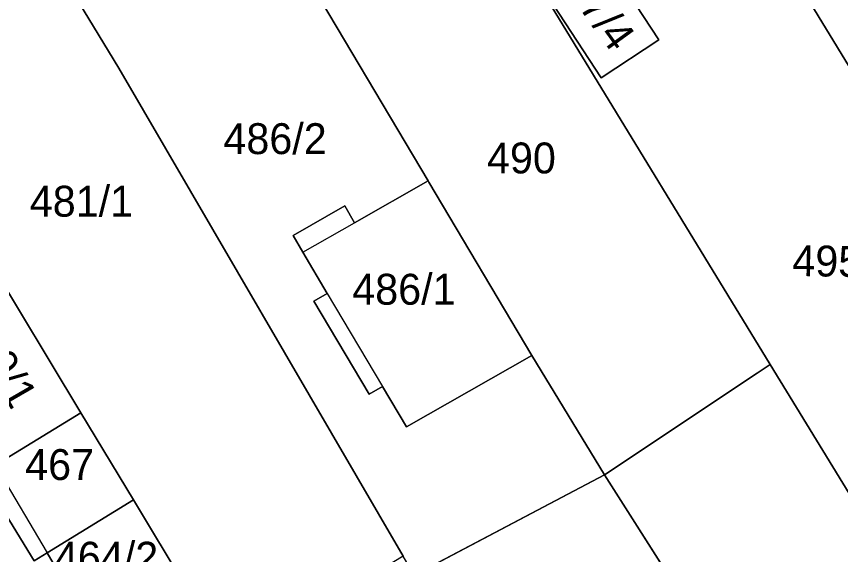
# Model space of a CAD drawing. Extents: x -263943 to -261149, y -1236934 to -1230686.
# Drawn here: x -262746.5 to -262693.2, y -1235535.8 to -1235500.9 of the extents above; entities that cross this region are included whole.
import ezdxf

# ---------------------------------------------------------------- set-up
doc = ezdxf.new("R2010")
doc.units = 0
for name, color, linetype in [('body_kn', 7, 'Continuous'), ('kladpar_druhypozemkov', 7, 'Continuous'), ('kladpar_hranice', 7, 'Continuous'), ('kladpar_parcelnecisla', 7, 'Continuous'), ('kladpar_plochy', 7, 'Continuous'), ('zappar_hrandruhpozemk', 7, 'Continuous')]:
    doc.layers.add(name, color=color, linetype=linetype)

msp = doc.modelspace()

# ---------------------------------------------------------------- linework, layer by layer
at = {"layer": 'body_kn'}
for p, q in [((-262704.92, -1235502.47), (-262704.92, -1235502.47)), ((-262739.92, -1235504.3), (-262739.92, -1235504.3)), ((-262708.67, -1235504.92), (-262708.67, -1235504.92)), ((-262719.87, -1235511.58), (-262719.87, -1235511.58)), ((-262719.82, -1235511.67), (-262719.82, -1235511.67)), ((-262725.27, -1235513.22), (-262725.27, -1235513.22)), ((-262724.65, -1235514.3), (-262724.65, -1235514.3)), ((-262728.61, -1235515.12), (-262728.61, -1235515.12)), ((-262728, -1235516.21), (-262728, -1235516.21)), ((-262728, -1235516.21), (-262728, -1235516.21)), ((-262726.41, -1235518.88), (-262726.41, -1235518.88)), ((-262726.41, -1235518.88), (-262726.41, -1235518.88)), ((-262727.27, -1235519.39), (-262727.27, -1235519.39)), ((-262713.16, -1235522.89), (-262713.16, -1235522.89)), ((-262697.71, -1235523.48), (-262697.71, -1235523.48)), ((-262698.56, -1235524.05), (-262698.56, -1235524.05)), ((-262722.84, -1235524.9), (-262722.84, -1235524.9)), ((-262722.84, -1235524.9), (-262722.84, -1235524.9)), ((-262723.7, -1235525.41), (-262723.7, -1235525.41)), ((-262723.7, -1235525.41), (-262723.7, -1235525.41)), ((-262742.37, -1235526.62), (-262742.37, -1235526.62)), ((-262721.28, -1235527.52), (-262721.28, -1235527.52)), ((-262708.44, -1235530.63), (-262708.44, -1235530.63)), ((-262708.44, -1235530.63), (-262708.44, -1235530.63)), ((-262738.97, -1235532.25), (-262738.97, -1235532.25)), ((-262744.56, -1235535.68), (-262744.56, -1235535.68)), ((-262744.56, -1235535.68), (-262744.56, -1235535.68))]:
    msp.add_line(p, q, dxfattribs=at)
at = {"layer": 'kladpar_druhypozemkov'}
for p, q in [((-262729.29, -1235507.92), (-262729.29, -1235507.92)), ((-262713.88, -1235509.06), (-262713.88, -1235509.06)), ((-262743.18, -1235511.56), (-262743.18, -1235511.56)), ((-262720.91, -1235517.64), (-262720.91, -1235517.64)), ((-262744.08, -1235529.36), (-262744.08, -1235529.36)), ((-262740.43, -1235535.31), (-262740.43, -1235535.31))]:
    msp.add_line(p, q, dxfattribs=at)
at = {"layer": 'kladpar_hranice'}
for points in [[(-262732.68, -1235542.66), (-262735.56, -1235537.92), (-262738.97, -1235532.25), (-262742.37, -1235526.62), (-262748.42, -1235516.59), (-262751.86, -1235510.9), (-262754.4, -1235506.7), (-262759.41, -1235498.41), (-262755.64, -1235496.17), (-262761.46, -1235480.43), (-262761.23, -1235480.29), (-262759.33, -1235483.39), (-262754.85, -1235480.58), (-262756.66, -1235477.56), (-262756.22, -1235477.3), (-262753.4, -1235482.02), (-262743.5, -1235498.38), (-262739.92, -1235504.3), (-262721.5, -1235535.89), (-262732.68, -1235542.66)], [(-262679.94, -1235550.86), (-262683.58, -1235545.66), (-262690.16, -1235535.81), (-262691.29, -1235533.96), (-262697.71, -1235523.48), (-262711.91, -1235500.27), (-262711.77, -1235500.18), (-262708.67, -1235504.92), (-262704.92, -1235502.47), (-262707.96, -1235497.85), (-262708.3, -1235498.02), (-262708.9, -1235497), (-262707.37, -1235494.42), (-262706.2, -1235493.57), (-262701.27, -1235490), (-262696.88, -1235497.18), (-262679.03, -1235526.4), (-262678.1, -1235528.02), (-262677.34, -1235529.21), (-262668.48, -1235542.55), (-262672.73, -1235545.63)], [(-262708.44, -1235530.63), (-262713.16, -1235522.89), (-262719.82, -1235511.67), (-262719.87, -1235511.58), (-262728.27, -1235497.45), (-262717.74, -1235491.26), (-262713.04, -1235498.53), (-262712.01, -1235500.12), (-262711.91, -1235500.27), (-262697.71, -1235523.48), (-262698.56, -1235524.05), (-262708.44, -1235530.63)], [(-262723.7, -1235525.41), (-262722.84, -1235524.9), (-262721.28, -1235527.52), (-262713.16, -1235522.89), (-262708.44, -1235530.63), (-262720.78, -1235537.12), (-262721.5, -1235535.89), (-262739.92, -1235504.3), (-262743.5, -1235498.38), (-262737.23, -1235494.67), (-262732.24, -1235491.71), (-262731.82, -1235491.46), (-262728.27, -1235497.45), (-262719.87, -1235511.58), (-262724.65, -1235514.3), (-262725.27, -1235513.22), (-262728.61, -1235515.12), (-262728, -1235516.21), (-262726.41, -1235518.88), (-262727.27, -1235519.39), (-262723.7, -1235525.41)], [(-262677.34, -1235529.21), (-262678.1, -1235528.02), (-262679.03, -1235526.4), (-262696.88, -1235497.18), (-262691.95, -1235494), (-262690.77, -1235493.24), (-262678.97, -1235512.32), (-262671.29, -1235524.22), (-262671.04, -1235524.56), (-262677.34, -1235529.21)], [(-262707.37, -1235494.42), (-262708.9, -1235497), (-262708.3, -1235498.02), (-262707.96, -1235497.85), (-262704.92, -1235502.47), (-262708.67, -1235504.92), (-262711.77, -1235500.18), (-262711.91, -1235500.27), (-262712.01, -1235500.12), (-262713.04, -1235498.53), (-262707.37, -1235494.42)], [(-262722.84, -1235524.9), (-262723.7, -1235525.41), (-262727.27, -1235519.39), (-262726.41, -1235518.88), (-262728, -1235516.21), (-262728.61, -1235515.12), (-262725.27, -1235513.22), (-262724.65, -1235514.3), (-262719.87, -1235511.58), (-262719.82, -1235511.67), (-262713.16, -1235522.89), (-262721.28, -1235527.52), (-262722.84, -1235524.9)], [(-262754.1, -1235519.97), (-262753.45, -1235519.58), (-262748.42, -1235516.59), (-262742.37, -1235526.62), (-262747.27, -1235529.61), (-262747.92, -1235530.01), (-262754.1, -1235519.97)], [(-262661.06, -1235580.01), (-262667.68, -1235584.04), (-262669.56, -1235581), (-262673.39, -1235583.28), (-262671.5, -1235586.37), (-262672.55, -1235587.01), (-262678.55, -1235577.58), (-262681.07, -1235573.62), (-262686.13, -1235565.68), (-262708.44, -1235530.63), (-262698.56, -1235524.05), (-262697.71, -1235523.48), (-262691.29, -1235533.96), (-262690.16, -1235535.81), (-262683.58, -1235545.66), (-262679.94, -1235550.86), (-262678.88, -1235552.37), (-262661.06, -1235580.01)], [(-262745.4, -1235536.19), (-262748.86, -1235530.58), (-262747.92, -1235530.01), (-262747.27, -1235529.61), (-262742.37, -1235526.62), (-262738.97, -1235532.25), (-262744.56, -1235535.68), (-262745.4, -1235536.19)], [(-262748.86, -1235530.58), (-262745.4, -1235536.19), (-262744.56, -1235535.68), (-262741.18, -1235541.47), (-262735.77, -1235548.28), (-262731.8, -1235554.23), (-262727.84, -1235560.95), (-262727.59, -1235562.73), (-262721.36, -1235572.81), (-262722.02, -1235573.19), (-262713.22, -1235586.8), (-262714.08, -1235587.33), (-262729.97, -1235563.83), (-262735.96, -1235553.03), (-262747.28, -1235537.2)], [(-262720.78, -1235537.12), (-262708.44, -1235530.63), (-262686.13, -1235565.68), (-262698.45, -1235573.07)], [(-262744.56, -1235535.68), (-262738.97, -1235532.25), (-262735.56, -1235537.92), (-262741.18, -1235541.47), (-262744.56, -1235535.68)]]:
    msp.add_lwpolyline(points, dxfattribs=at)
at = {"layer": 'kladpar_plochy'}
for p, q in [((-262720.78, -1235537.12), (-262708.44, -1235530.63)), ((-262708.44, -1235530.63), (-262686.13, -1235565.68))]:
    msp.add_line(p, q, dxfattribs=at)
for points in [[(-262732.68, -1235542.66), (-262735.56, -1235537.92), (-262738.97, -1235532.25), (-262742.37, -1235526.62), (-262748.42, -1235516.59), (-262751.86, -1235510.9), (-262754.4, -1235506.7), (-262759.41, -1235498.41), (-262755.64, -1235496.17), (-262761.46, -1235480.43), (-262761.23, -1235480.29), (-262759.33, -1235483.39), (-262754.85, -1235480.58), (-262756.66, -1235477.56), (-262756.22, -1235477.3), (-262753.4, -1235482.02), (-262743.5, -1235498.38), (-262739.92, -1235504.3), (-262721.5, -1235535.89)], [(-262679.94, -1235550.86), (-262683.58, -1235545.66), (-262690.16, -1235535.81), (-262691.29, -1235533.96), (-262697.71, -1235523.48), (-262711.91, -1235500.27), (-262711.77, -1235500.18), (-262708.67, -1235504.92), (-262704.92, -1235502.47), (-262707.96, -1235497.85), (-262708.3, -1235498.02), (-262708.9, -1235497), (-262707.37, -1235494.42), (-262706.2, -1235493.57), (-262701.27, -1235490), (-262696.88, -1235497.18), (-262679.03, -1235526.4), (-262678.1, -1235528.02), (-262677.34, -1235529.21), (-262668.48, -1235542.55), (-262672.73, -1235545.63), (-262685.17, -1235526.28), (-262686.8, -1235527.37), (-262674.32, -1235546.78)], [(-262708.44, -1235530.63), (-262713.16, -1235522.89), (-262719.82, -1235511.67), (-262719.87, -1235511.58), (-262728.27, -1235497.45), (-262717.74, -1235491.26), (-262713.04, -1235498.53), (-262712.01, -1235500.12), (-262711.91, -1235500.27), (-262697.71, -1235523.48), (-262698.56, -1235524.05)], [(-262723.7, -1235525.41), (-262722.84, -1235524.9), (-262721.28, -1235527.52), (-262713.16, -1235522.89), (-262708.44, -1235530.63), (-262720.78, -1235537.12), (-262721.5, -1235535.89), (-262739.92, -1235504.3), (-262743.5, -1235498.38), (-262737.23, -1235494.67), (-262732.24, -1235491.71), (-262731.82, -1235491.46), (-262728.27, -1235497.45), (-262719.87, -1235511.58), (-262724.65, -1235514.3), (-262725.27, -1235513.22), (-262728.61, -1235515.12), (-262728, -1235516.21), (-262726.41, -1235518.88), (-262727.27, -1235519.39)], [(-262677.34, -1235529.21), (-262678.1, -1235528.02), (-262679.03, -1235526.4), (-262696.88, -1235497.18), (-262691.95, -1235494), (-262690.77, -1235493.24), (-262678.97, -1235512.32), (-262671.29, -1235524.22), (-262671.04, -1235524.56)], [(-262707.37, -1235494.42), (-262708.9, -1235497), (-262708.3, -1235498.02), (-262707.96, -1235497.85), (-262704.92, -1235502.47), (-262708.67, -1235504.92), (-262711.77, -1235500.18), (-262711.91, -1235500.27), (-262712.01, -1235500.12), (-262713.04, -1235498.53)], [(-262722.84, -1235524.9), (-262723.7, -1235525.41), (-262727.27, -1235519.39), (-262726.41, -1235518.88), (-262728, -1235516.21), (-262728.61, -1235515.12), (-262725.27, -1235513.22), (-262724.65, -1235514.3), (-262719.87, -1235511.58), (-262719.82, -1235511.67), (-262713.16, -1235522.89), (-262721.28, -1235527.52)], [(-262754.1, -1235519.97), (-262753.45, -1235519.58), (-262748.42, -1235516.59), (-262742.37, -1235526.62), (-262747.27, -1235529.61), (-262747.92, -1235530.01)], [(-262661.06, -1235580.01), (-262667.68, -1235584.04), (-262669.56, -1235581), (-262673.39, -1235583.28), (-262671.5, -1235586.37), (-262672.55, -1235587.01), (-262678.55, -1235577.58), (-262681.07, -1235573.62), (-262686.13, -1235565.68), (-262708.44, -1235530.63), (-262698.56, -1235524.05), (-262697.71, -1235523.48), (-262691.29, -1235533.96), (-262690.16, -1235535.81), (-262683.58, -1235545.66), (-262679.94, -1235550.86), (-262678.88, -1235552.37)], [(-262745.4, -1235536.19), (-262748.86, -1235530.58), (-262747.92, -1235530.01), (-262747.27, -1235529.61), (-262742.37, -1235526.62), (-262738.97, -1235532.25), (-262744.56, -1235535.68)], [(-262744.56, -1235535.68), (-262738.97, -1235532.25), (-262735.56, -1235537.92), (-262741.18, -1235541.47)]]:
    msp.add_lwpolyline(points, close=True, dxfattribs=at)
msp.add_lwpolyline([(-262748.86, -1235530.58), (-262745.4, -1235536.19), (-262744.56, -1235535.68), (-262741.18, -1235541.47), (-262735.77, -1235548.28), (-262731.8, -1235554.23), (-262727.84, -1235560.95), (-262727.59, -1235562.73), (-262721.36, -1235572.81), (-262722.02, -1235573.19), (-262713.22, -1235586.8), (-262714.08, -1235587.33), (-262729.97, -1235563.83), (-262735.96, -1235553.03), (-262747.28, -1235537.2)], dxfattribs=at)
at = {"layer": 'zappar_hrandruhpozemk'}
for p, q in [((-262728, -1235516.21), (-262724.65, -1235514.3)), ((-262726.41, -1235518.88), (-262722.84, -1235524.9)), ((-262747.92, -1235530.01), (-262744.56, -1235535.68))]:
    msp.add_line(p, q, dxfattribs=at)

# ---------------------------------------------------------------- texts
at = {"layer": 'kladpar_parcelnecisla'}
for s, rotation, p in [('497/4', 306, (-262711.905, -1235497.928)), ('495/1', 359, (-262696.292, -1235517.746)), ('470/1', 300, (-262750.183, -1235520.7))]:
    msp.add_text(s, height=2, rotation=rotation, dxfattribs=at).set_placement(p)
for s, p in [('486/2', (-262733.137, -1235509.86)), ('490', (-262716.06, -1235511.11)), ('481/1', (-262745.682, -1235513.91)), ('486/1', (-262724.791, -1235519.61)), ('467', (-262745.982, -1235530.96)), ('464/2', (-262744.056, -1235536.96))]:
    msp.add_text(s, height=2, dxfattribs=at).set_placement(p)

doc.saveas('drawing.dxf')
